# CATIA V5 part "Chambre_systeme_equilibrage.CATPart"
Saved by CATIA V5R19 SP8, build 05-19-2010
Part number: Chambre_systeme_equilibrage
Bounding box of the stored display mesh (mm): x -130.438 to -75, y -615.434 to -64.826, z 1202.311 to 1314.328
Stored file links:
  G:\EU_thinkMotion\CFAO_2010\MMS_groupe2\MMS_groupe2\OK\nrosalie\nrosalie_cfao_support_d_arme_legere_final\Chambre_systeme_equilibrage.CATPart
  G:\EU_thinkMotion\CFAO_2010\MMS_groupe2\MMS_groupe2\OK\nrosalie\nrosalie_cfao_support_d_arme_legere_final\nrosalie_Support_d_arme_legere.CATProduct
  G:\EU_thinkMotion\CFAO_2010\MMS_groupe2\MMS_groupe2\OK\nrosalie\nrosalie_cfao_support_d_arme_legere_final\Squelette_systeme_d_equilibrage.CATPart
  G:\EU_thinkMotion\CFAO_2010\MMS_groupe2\MMS_groupe2\OK\nrosalie\nrosalie_cfao_support_d_arme_legere_final\Squelette_piece_support.CATPart
  G:\EU_thinkMotion\CFAO_2010\MMS_groupe2\MMS_groupe2\OK\nrosalie\nrosalie_cfao_support_d_arme_legere_final\Bras.CATPart
  G:\EU_thinkMotion\CFAO_2010\MMS_groupe2\MMS_groupe2\OK\nrosalie\nrosalie_cfao_support_d_arme_legere_final\Squelette_bras.CATPart
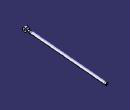
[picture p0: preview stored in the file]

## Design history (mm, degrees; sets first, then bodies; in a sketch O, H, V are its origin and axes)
Set1
  Plane1: linked copy from another document
  Point1: linked copy from another document
  Plane2: linked copy from another document
  DatumPoint1 to DatumPoint5: linked copy from another document
  Line1: linked copy from another document
  Line2: linked copy from another document
  DatumCurve1: linked copy from another document
  Line3: linked copy from another document
  DatumCurve2: linked copy from another document
  DatumSurface1: linked copy from another document
Body1 (main body)
  Plane3: type OffsetPt, RefPlane zx-plane, RefPoint DatumPoint2
  Sketch1 on Plane3, origin (0, -600.5571, 0), H (-1, 0, 0), V (0, 0, 1)
    line L1 (95, 1314.4514) -> (75, 1314.4514)
    line L2 (75, 1314.4514) -> (75, 1304.4514)
    line L3 (75, 1304.4514) -> (95, 1304.4514)
    line L4 (95, 1304.4514) -> (95, 1314.4514)
    reference projected point E3 (85, 1299.4514) from vertex of DatumPoint2
    reference projected line E4 (95, 1604.3762) -> (95, 1594.3762) from edge of DatumCurve1
    distance E3 L3 = 5
    distance L3 L1 = 10
    distance L2 L4 = 20
    horizontal: L1 H, L3 H
    coincidence: L4 E4
  Shaft1: profile Sketch1, axis edge of DatumCurve2, angle 360
  Sketch2 on Plane2, origin (51.9908, -780.0682, 145.3957), H (0.9978, 0.0663, 0), V (-0.0107, 0.1606, 0.987)
    circle A1 centre (-124.7431, 1169.3051) radius 5
    point P1 (-124.7431, 1169.3051)
    reference projected point E1 (-124.7431, 1169.3051) from Line2
    radius A1 = 5
    coincidence: P1 E1
  Pad1: profile Sketch2, direction (-0.0654, 0.9848, -0.1609), length 30, opposite side up to face of Shaft1 from Sketch1.L1
  Sketch3 on end face of Pad1, origin (50.0411, -750.6317, 139.9056), H (-0.9978, -0.0663, 0), V (-0.0107, 0.1606, 0.987)
    circle A1 centre (124.7481, 1169.9756) radius 10
    reference projected circle E1 centre (124.7481, 1169.9756) radius 5 from edge [end face of Pad1 | face of Pad1 from Sketch2.A1]
    radius A1 = 10
    concentricity: E1 A1
  Pad2: profile Sketch3, direction (-0.0654, 0.9848, -0.1609), up to Plane1, offset -100
  Sketch4 on end face of Pad2, origin (16.5342, -248.0288, 46.1677), H (-0.9978, -0.0663, 0), V (-0.0107, 0.1606, 0.987)
    circle A1 centre (124.6169, 1181.4202) radius 5
    reference projected circle E1 centre (124.6169, 1181.4202) radius 10 from edge [end face of Pad2 | face of Pad2 from Sketch3.A1]
    radius A1 = 5
    concentricity: A1 E1
  Pocket1: profile Sketch4, direction (0.0654, -0.9848, 0.1609), length 30
  Sketch5 on end face of Pad2, origin (16.5342, -248.0288, 46.1677), H (-0.9978, -0.0663, 0), V (-0.0107, 0.1606, 0.987)
    circle A1 centre (124.6169, 1181.4202) radius 9
    reference projected circle E1 centre (124.6169, 1181.4202) radius 10 from edge [end face of Pad2 | face of Pad2 from Sketch3.A1]
    radius A1 = 9
    concentricity: A1 E1
  Pocket2: profile Sketch5, direction (0.0654, -0.9848, 0.1609), up to start face of Pad2, offset -10, opposite side up to end face of Pad2, offset -10
  Line4: type PtPt, FirstPoint DatumPoint2, SecondPoint Point1, Start 500, End 500
  Line5: type PtPt, FirstPoint DatumPoint2, SecondPoint DatumPoint1, Start 20
  Plane4: type Normal, Curve Line5, RefPoint DatumPoint2
  Plane5: type 3Points, Element1 DatumPoint3, Element2 DatumPoint4, Element3 DatumPoint5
